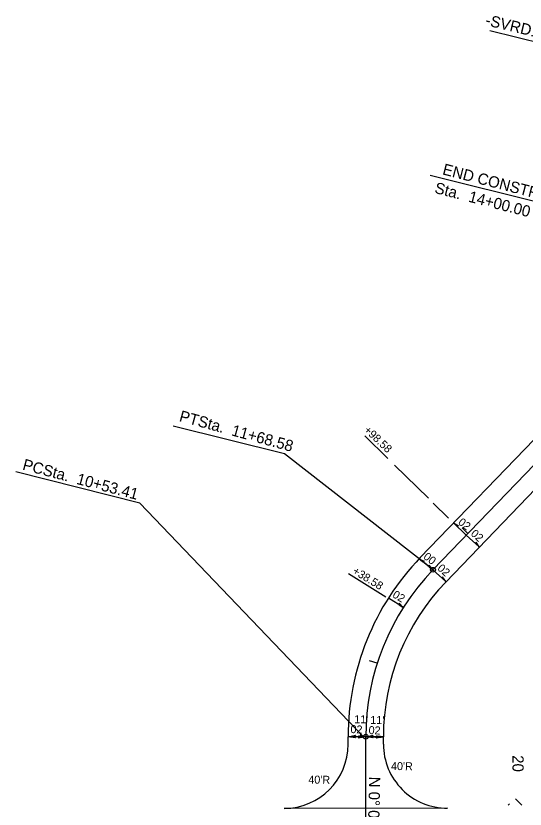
# Model space of a CAD drawing. Extents: x 2389099 to 2405615, y 552200 to 573532.
# Drawn here: x 2397399.3 to 2397717.2, y 559465.7 to 559960.9 of the extents above; entities that cross this region are included whole.
import ezdxf

# ---------------------------------------------------------------- set-up
doc = ezdxf.new("R2010")
doc.units = 0
for name, color, linetype in [('Prop Dimension', 7, 'Continuous'), ('Prop Dimension Text', 7, 'Continuous'), ('Prop EOT', 7, 'Continuous'), ('Prop Hatching', 7, 'Continuous'), ('Prop Horizontal Alignment', 7, 'Continuous'), ('Prop Horizontal Alignment Curve and Spiral Data', 7, 'Continuous'), ('Prop Horizontal Alignment Direction Label', 7, 'Continuous'), ('Prop Horizontal Alignment Station Label', 7, 'Continuous'), ('Prop Horizontal Alignment Tick Small', 7, 'Continuous'), ('Prop Super Arrow 1 Lane CELL', 7, 'Continuous'), ('Prop Superelevation Label', 7, 'Continuous')]:
    doc.layers.add(name, color=color, linetype=linetype)

msp = doc.modelspace()

# ---------------------------------------------------------------- linework, layer by layer
at = {"layer": 'Prop Dimension'}
for p, q in [((2397617.07, 559698.72), (2397631.45, 559684.63)), ((2397635.75, 559680.41), (2397656.82, 559659.78)), ((2397659.9, 559656.76), (2397669.4, 559647.45)), ((2397606.9, 559612.91), (2397630.35, 559598.29)), ((2397617.72, 559510.9), (2397606.72, 559510.89)), ((2397617.72, 559510.9), (2397628.72, 559510.91))]:
    msp.add_line(p, q, dxfattribs=at)
for points in [[(2397611.25, 559510.28), (2397606.72, 559510.89), (2397611.22, 559511.85), (2397610.67, 559511.03)], [(2397613.2, 559511.51), (2397617.72, 559510.9), (2397613.23, 559509.93), (2397613.78, 559510.75)], [(2397622.25, 559510.29), (2397617.72, 559510.9), (2397622.22, 559511.87), (2397621.67, 559511.05)], [(2397624.2, 559511.52), (2397628.72, 559510.91), (2397624.23, 559509.95), (2397624.78, 559510.77)]]:
    msp.add_lwpolyline(points, close=True, dxfattribs=at)
at = {"layer": 'Prop EOT'}
for p, q in [((2397651.77, 559622.77), (2397777.64, 559753.44)), ((2397667.61, 559607.5), (2397793.49, 559738.19)), ((2397606.73, 559506.23), (2397606.72, 559510.89)), ((2397628.73, 559506.26), (2397628.72, 559510.91)), ((2397668.78, 559466.3), (2397566.78, 559466.18))]:
    msp.add_line(p, q, dxfattribs=at)
for centre, radius, start, end in [((2397767.72, 559511.07), 161, 136.0726, 180.0667), ((2397767.72, 559511.07), 139, 136.0726, 180.0667), ((2397566.73, 559506.18), 40, 270.0667, 0.0667), ((2397668.73, 559506.3), 40, 180.0667, 270.0667)]:
    msp.add_arc(centre, radius, start, end, dxfattribs=at)
at = {"layer": 'Prop Hatching'}
for p, q in [((2397706.66, 559468.12), (2397707.52, 559468.98)), ((2397715.14, 559468.14), (2397711.18, 559472.1))]:
    msp.add_line(p, q, dxfattribs=at)
at = {"layer": 'Prop Horizontal Alignment'}
for p, q in [((2397659.69, 559615.14), (2397920.45, 559885.84)), ((2397617.79, 559457.49), (2397617.72, 559510.9))]:
    msp.add_line(p, q, dxfattribs=at)
msp.add_arc((2397767.72, 559511.07), 150, 136.0726, 180.0667, dxfattribs=at)
at = {"layer": 'Prop Horizontal Alignment Curve and Spiral Data'}
for p, q in [((2397817.95, 559920.95), (2397695.08, 559951.59)), ((2397759.41, 559835.92), (2397657.87, 559861.24))]:
    msp.add_line(p, q, dxfattribs=at)
at = {"layer": 'Prop Horizontal Alignment Station Label'}
for p, q in [((2397567.04, 559687.54), (2397497.51, 559704.87)), ((2397658.61, 559616.18), (2397567.04, 559687.54)), ((2397476.62, 559656.78), (2397399.28, 559676.2)), ((2397616.22, 559510.9), (2397476.62, 559656.78))]:
    msp.add_line(p, q, dxfattribs=at)
for centre in [(2397659.69, 559615.14), (2397617.72, 559510.9)]:
    msp.add_circle(centre, 1.5, dxfattribs=at)
at = {"layer": 'Prop Horizontal Alignment Tick Small'}
for p, q in [((2397681.49, 559637.76), (2397677.89, 559641.23)), ((2397624.85, 559556.76), (2397620.09, 559558.28))]:
    msp.add_line(p, q, dxfattribs=at)
at = {"layer": 'Prop Super Arrow 1 Lane CELL'}
for p, q in [((2397680.45, 559636.78), (2397672.57, 559644.45)), ((2397688.61, 559629.4), (2397680.45, 559636.78)), ((2397659.62, 559615.16), (2397650.96, 559621.94)), ((2397667.78, 559607.79), (2397659.62, 559615.16)), ((2397641.29, 559591.62), (2397631.96, 559597.46)), ((2397617.78, 559510.87), (2397606.72, 559510.89)), ((2397628.72, 559510.91), (2397617.76, 559510.85))]:
    msp.add_line(p, q, dxfattribs=at)
for points in [[(2397672.5, 559644.54), (2397675.54, 559642.63), (2397674.59, 559642.45)], [(2397688.61, 559629.4), (2397686.55, 559632.34), (2397686.42, 559631.38)], [(2397650.88, 559622.01), (2397654.11, 559620.45), (2397653.18, 559620.17)], [(2397659.62, 559615.16), (2397657.38, 559617.97), (2397657.31, 559617)], [(2397667.78, 559607.79), (2397665.72, 559610.73), (2397665.6, 559609.77)], [(2397641.17, 559591.66), (2397638.63, 559594.19), (2397638.67, 559593.22)], [(2397617.66, 559510.84), (2397614.21, 559511.83), (2397614.72, 559511)], [(2397628.72, 559510.91), (2397625.29, 559511.25), (2397625.8, 559510.42)]]:
    msp.add_lwpolyline(points, close=True, dxfattribs=at)

# ---------------------------------------------------------------- texts
at = {"layer": 'Prop Dimension Text'}
for s, rotation, p in [('+98.58', 316.6196, (2397616.21, 559701.88)), ('+38.58', 328.5774, (2397609, 559613.1)), ("11'", 359.143, (2397610.48, 559519.37)), ("11'", 359.143, (2397620.56, 559518.93)), ("40'R", 359.143, (2397633.47, 559490.16)), ("40'R", 359.143, (2397581.86, 559481.7))]:
    msp.add_text(s, height=5, rotation=rotation, dxfattribs=at).set_placement(p)
at = {"layer": 'Prop Horizontal Alignment Curve and Spiral Data'}
for s, rotation, p in [('-SVRD1- POT Sta.15+44.45  ', 346.6546, (2397691.93, 559955.18)), ('END CONSTRUCTION', 345.53, (2397665.18, 559862.05)), ('Sta.  14+00.00', 345.53, (2397660.24, 559850.46)), ('20', 270.0667, (2397709.28, 559499.38))]:
    msp.add_text(s, height=7, rotation=rotation, dxfattribs=at).set_placement(p)
at = {"layer": 'Prop Horizontal Alignment Direction Label'}
msp.add_text('N 0%%d 04\' 00.1" W', height=7, rotation=268.7132, dxfattribs=at).set_placement((2397619.81, 559486.06))
at = {"layer": 'Prop Horizontal Alignment Station Label'}
for s, rotation, p in [('PTSta.  11+68.58', 344.7002, (2397500.82, 559708.03)), ('PCSta.  10+53.41', 345.1645, (2397403, 559677.74))]:
    msp.add_text(s, height=7, rotation=rotation, dxfattribs=at).set_placement(p)
at = {"layer": 'Prop Superelevation Label'}
for s, rotation, p in [('02', 321.9985, (2397674.94, 559644)), ('02', 317.8867, (2397682.85, 559637.14)), ('00', 321.9985, (2397653.26, 559622.49)), ('02', 317.8867, (2397662.02, 559615.53)), ('02', 327.9714, (2397633.96, 559598.39)), ('02', 356.9593, (2397608.09, 559513.24)), ('02', 356.9593, (2397619.39, 559512.64))]:
    msp.add_text(s, height=5, rotation=rotation, dxfattribs=at).set_placement(p)

doc.saveas('drawing.dxf')
